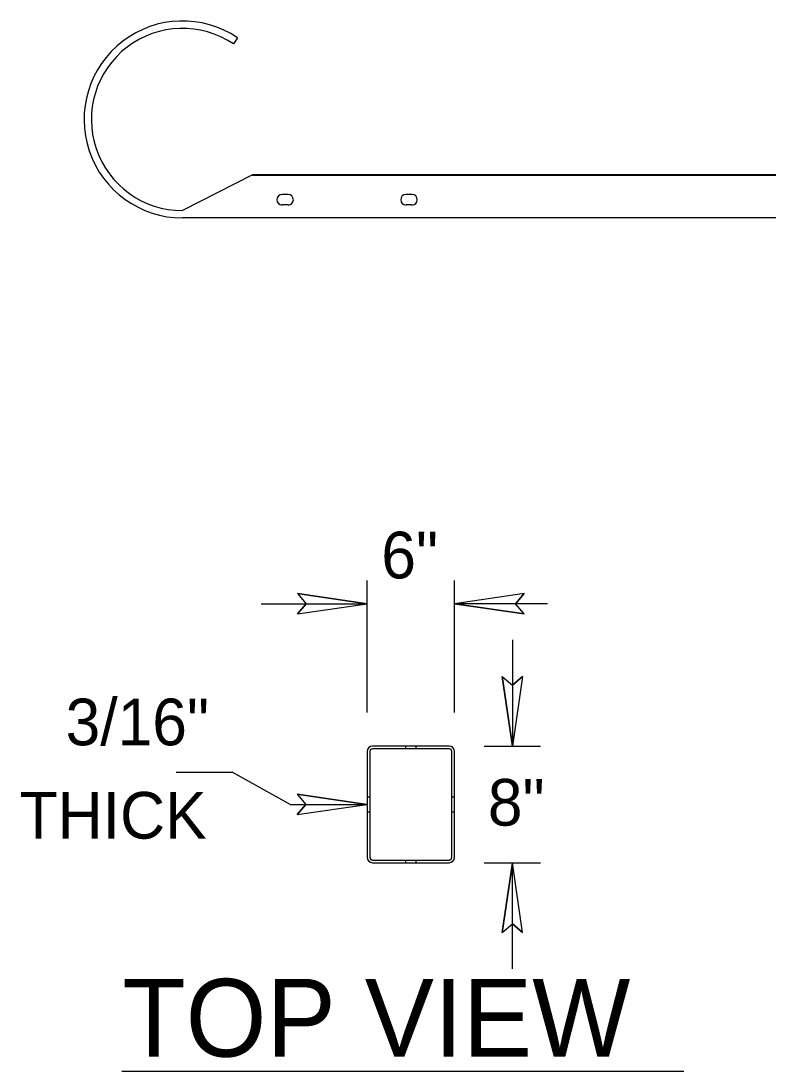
# Model space of a CAD drawing. Extents: x 12.2 to 54.5, y -7.8 to 16.1.
# Drawn here: x 12.556 to 13.517, y 10.89 to 12.24 of the extents above; entities that cross this region are included whole.
import ezdxf

# ---------------------------------------------------------------- set-up
doc = ezdxf.new("R2010")
doc.units = 0
for name, color, linetype in [('BORD-LINE', 7, 'Continuous'), ('DETAIL DIM', 7, 'Continuous'), ('DETL-DIMS', 7, 'Continuous'), ('DETL-NOTE', 7, 'Continuous'), ('DETL-TITL', 7, 'Continuous')]:
    doc.layers.add(name, color=color, linetype=linetype)

msp = doc.modelspace()

# ---------------------------------------------------------------- linework, layer by layer
at = {"layer": 'BORD-LINE'}
for p, q in [((12.8343, 12.2183), (12.8291, 12.2105)), ((12.8535, 12.0419), (12.7636, 11.9961)), ((13.6378, 12.0419), (12.8535, 12.0419)), ((16.7435, 12.0412), (12.8535, 12.0414)), ((12.8995, 12.0169), (12.8918, 12.0169)), ((13.0589, 12.0169), (13.0511, 12.0169)), ((12.8995, 12.0034), (12.8918, 12.0034)), ((13.0589, 12.0034), (13.0512, 12.0034)), ((16.7308, 11.9868), (12.7636, 11.9868)), ((13.0011, 11.3006), (13.0011, 11.1647)), ((13.0047, 11.3006), (13.0047, 11.1647)), ((13.1066, 11.3076), (13.0082, 11.3076)), ((13.1066, 11.3041), (13.0082, 11.3041)), ((13.1101, 11.1647), (13.1101, 11.3006)), ((13.1136, 11.1647), (13.1136, 11.3006)), ((13.0082, 11.1611), (13.1066, 11.1611)), ((13.0082, 11.1576), (13.1066, 11.1576))]:
    msp.add_line(p, q, dxfattribs=at)
for centre, radius, start, end in [((12.7636, 12.1133), 0.1266, 56.0461, 270), ((12.7636, 12.1133), 0.1172, 56.0463, 270), ((12.8918, 12.0101), 0.0068, 90.1896, 270.0253), ((12.8995, 12.0101), 0.0068, 269.9747, 89.8104), ((13.0512, 12.0101), 0.0068, 90.1896, 270.0253), ((13.0589, 12.0101), 0.0068, 269.9747, 89.8104), ((13.0082, 11.3006), 0.00703, 90, 180), ((13.0082, 11.3006), 0.00352, 90, 180), ((13.1066, 11.3006), 0.00703, 0, 90), ((13.1066, 11.3006), 0.00352, 0, 90), ((13.0082, 11.1647), 0.00703, 180, 270), ((13.0082, 11.1647), 0.00352, 180, 270), ((13.1066, 11.1647), 0.00352, 270, 360), ((13.1066, 11.1647), 0.00703, 270, 0)]:
    msp.add_arc(centre, radius, start, end, dxfattribs=at)
for points in [[(13.0504, 11.3076), (13.0504, 11.3041)], [(13.0644, 11.3041), (13.0644, 11.3076)], [(13.0047, 11.242), (13.0011, 11.242)], [(13.1136, 11.242), (13.1101, 11.242)], [(13.0011, 11.2232), (13.0047, 11.2232)], [(13.1101, 11.2232), (13.1136, 11.2232)], [(13.0504, 11.1611), (13.0504, 11.1576)], [(13.0644, 11.1576), (13.0644, 11.1611)]]:
    msp.add_open_spline(points, degree=1, dxfattribs=at)
at = {"layer": 'DETAIL DIM'}
for p, q in [((12.8647, 11.4907), (13.0011, 11.4907)), ((13.2331, 11.4907), (13.1136, 11.4907)), ((13.188, 11.4441), (13.188, 11.3076)), ((13.188, 11.0211), (13.188, 11.1576))]:
    msp.add_line(p, q, dxfattribs=at)
at = {"layer": 'DETL-DIMS'}
for p, q in [((13.0011, 11.3507), (13.0011, 11.5205)), ((13.1136, 11.3507), (13.1136, 11.5205)), ((12.9115, 11.5039), (13.0011, 11.4907)), ((12.9115, 11.5039), (12.9226, 11.4907)), ((13.2032, 11.5036), (13.1136, 11.4907)), ((13.2032, 11.5036), (13.1921, 11.4907)), ((12.9115, 11.4778), (13.0011, 11.4907)), ((12.9115, 11.4778), (12.9226, 11.4907)), ((13.2032, 11.4775), (13.1136, 11.4907)), ((13.2032, 11.4775), (13.1921, 11.4907)), ((13.1748, 11.3972), (13.188, 11.3076)), ((13.1748, 11.3972), (13.188, 11.3861)), ((13.2009, 11.3972), (13.188, 11.3076)), ((13.2009, 11.3972), (13.188, 11.3861)), ((13.1519, 11.3076), (13.2241, 11.3076)), ((12.7553, 11.2742), (12.8274, 11.2742)), ((12.9022, 11.2326), (12.8274, 11.2742)), ((12.9022, 11.2326), (13.0011, 11.2326)), ((12.9113, 11.2458), (13.0009, 11.2326)), ((12.9113, 11.2458), (12.9224, 11.2326)), ((12.9113, 11.2197), (13.0009, 11.2326)), ((12.9113, 11.2197), (12.9224, 11.2326)), ((13.1519, 11.1576), (13.2241, 11.1576)), ((13.1748, 11.068), (13.188, 11.1576)), ((13.2009, 11.068), (13.188, 11.1576)), ((13.1748, 11.068), (13.188, 11.0791)), ((13.2009, 11.068), (13.188, 11.0791))]:
    msp.add_line(p, q, dxfattribs=at)
for points in [[(12.9115, 11.4778), (13.0011, 11.4907), (12.9115, 11.5039), (12.9226, 11.4907)], [(13.2032, 11.5036), (13.1136, 11.4907), (13.2032, 11.4775), (13.1921, 11.4907)], [(13.2009, 11.3972), (13.188, 11.3076), (13.1748, 11.3972), (13.188, 11.3861)], [(12.9113, 11.2197), (13.0009, 11.2326), (12.9113, 11.2458), (12.9224, 11.2326)], [(13.2009, 11.068), (13.188, 11.1576), (13.1748, 11.068), (13.188, 11.0791)]]:
    msp.add_lwpolyline(points, close=True, dxfattribs=at)
at = {"layer": 'DETL-TITL'}
msp.add_line((12.6854, 10.8898), (13.4086, 10.8898), dxfattribs=at)

# ---------------------------------------------------------------- texts
at = {"layer": 'DETL-NOTE'}
for s, p in [('6"', (13.0194, 11.5232)), ('3/16"', (12.6132, 11.3086)), ('8"', (13.1565, 11.2053)), ('THICK', (12.554, 11.1886))]:
    msp.add_text(s, height=0.06, dxfattribs=at).set_placement(p)
at = {"layer": 'DETL-TITL'}
msp.add_text('TOP VIEW', height=0.1, dxfattribs=at).set_placement((12.686, 10.9083))

doc.saveas('drawing.dxf')
